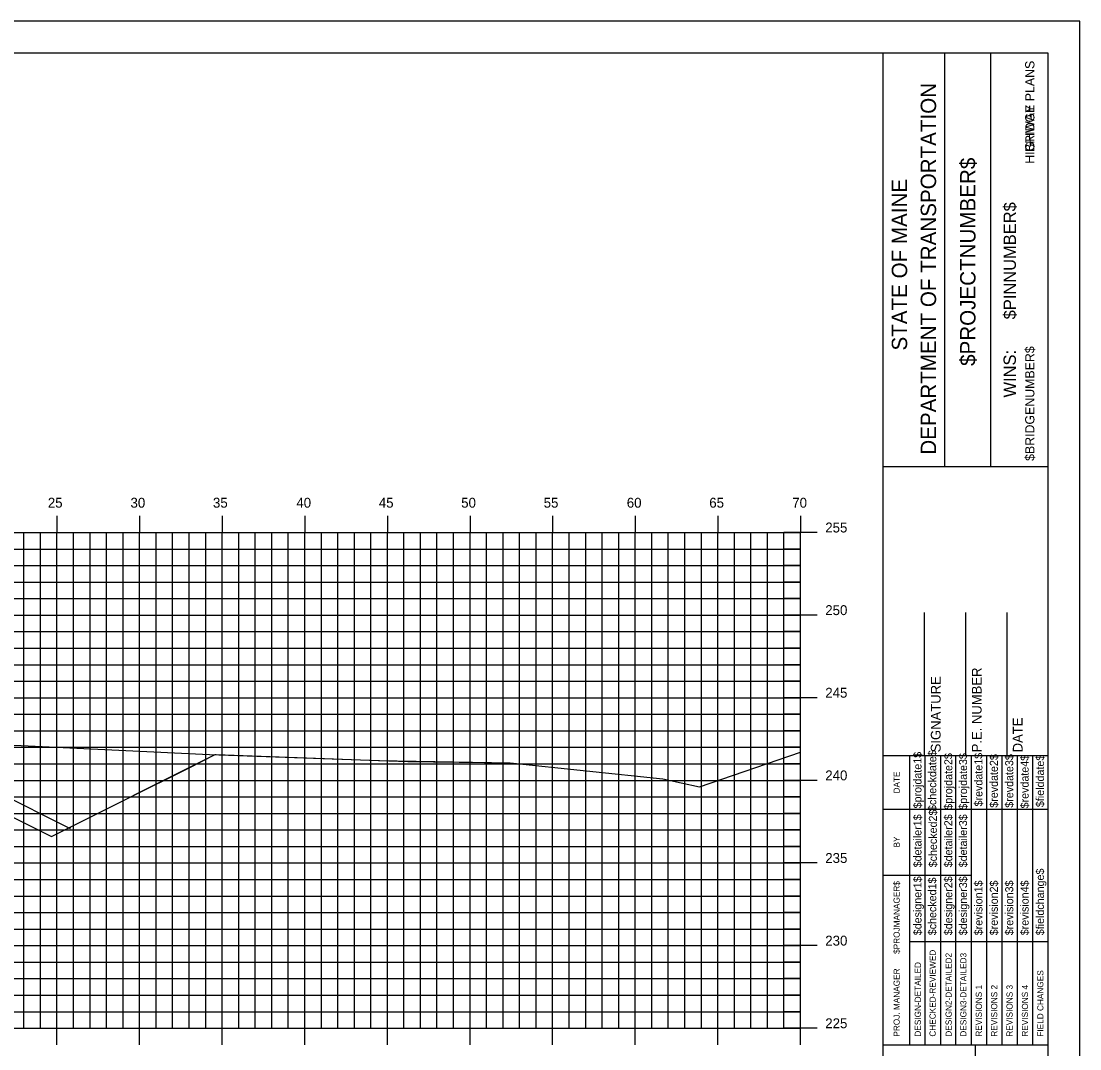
# Model space of a CAD drawing. Extents: x 1168600 to 1177589, y 610178 to 611246.
# Drawn here: x 1173212.4 to 1173276.5, y 610948.3 to 611010.5 of the extents above; entities that cross this region are included whole.
import ezdxf

# ---------------------------------------------------------------- set-up
doc = ezdxf.new("R2010")
doc.units = 0
for name, color, linetype in [('_Construction', 7, 'Continuous'), ('_Station Equation', 7, 'Continuous'), ('BORDER', 7, 'Continuous'), ('D_Text_Standard', 7, 'Continuous'), ('H_V ANNOTATION', 7, 'Continuous'), ('MAJOR', 7, 'Continuous'), ('MINOR', 7, 'Continuous')]:
    doc.layers.add(name, color=color, linetype=linetype)

msp = doc.modelspace()

# ---------------------------------------------------------------- linework, layer by layer
at = {"layer": '_Construction'}
for p, q in [((1173274.585, 611008.596), (1173114.585, 611008.596)), ((1173264.585, 610903.599), (1173264.585, 611008.599)), ((1173268.314, 610983.593), (1173268.314, 611008.593)), ((1173271.109, 610983.593), (1173271.109, 611008.593)), ((1173274.585, 610903.599), (1173274.585, 611008.599)), ((1173264.586, 610983.59), (1173274.585, 610983.59)), ((1173267.085, 610966.099), (1173267.085, 610974.747)), ((1173269.585, 610966.099), (1173269.585, 610974.747)), ((1173272.085, 610966.099), (1173272.085, 610974.747)), ((1173264.585, 610966.099), (1173274.585, 610966.099)), ((1173264.585, 610948.599), (1173274.585, 610948.599)), ((1173270.176, 610913.599), (1173270.176, 610948.599))]:
    msp.add_line(p, q, dxfattribs=at)
msp.add_lwpolyline([(1173106.492, 610900.537), (1173276.492, 610900.537), (1173276.492, 611010.537), (1173106.492, 611010.537)], close=True, dxfattribs=at)
for points in [[(1173266.2, 610962.849), (1173266.2, 610966.099)], [(1173267.132, 610948.602), (1173267.132, 610966.099)], [(1173268.064, 610966.099), (1173268.064, 610948.602)], [(1173268.996, 610948.602), (1173268.996, 610966.099)], [(1173269.928, 610948.602), (1173269.928, 610966.099)], [(1173270.859, 610948.602), (1173270.859, 610966.099)], [(1173271.791, 610948.602), (1173271.791, 610966.099)], [(1173272.723, 610948.602), (1173272.723, 610966.099)], [(1173273.654, 610948.602), (1173273.654, 610966.099)], [(1173266.201, 610948.602), (1173266.201, 610965.393)], [(1173264.585, 610962.849), (1173274.585, 610962.849)], [(1173264.585, 610958.849), (1173266.201, 610958.849)], [(1173266.2, 610958.849), (1173269.927, 610958.849)], [(1173266.2, 610954.849), (1173274.585, 610954.849)]]:
    msp.add_lwpolyline(points, dxfattribs=at)
at = {"layer": '_Station Equation'}
for points in [[(1173119.584, 610974.506), (1173125.722, 610972.617), (1173130.418, 610971.209), (1173135.169, 610970.962), (1173171.23, 610968.586), (1173185.811, 610967.653), (1173195.611, 610967.327), (1173212.422, 610966.698), (1173223.82, 610966.167), (1173235.815, 610965.745), (1173242.003, 610965.653), (1173251.256, 610964.689), (1173253.478, 610964.205), (1173259.584, 610966.307)], [(1173210.871, 610963.945), (1173215.374, 610961.692), (1173215.378, 610961.7), (1173215.424, 610961.784), (1173215.506, 610961.825), (1173215.978, 610962.061), (1173216.23, 610962.187), (1173216.95, 610962.547), (1173218.934, 610963.539), (1173222.535, 610965.339), (1173224.166, 610966.155), (1173224.216, 610966.153), (1173234.051, 610965.807), (1173242.003, 610965.653), (1173251.256, 610964.689), (1173253.478, 610964.205), (1173259.584, 610966.307)]]:
    msp.add_lwpolyline(points, dxfattribs=at)
at = {"layer": 'D_Text_Standard'}
msp.add_lwpolyline([(1173152.164, 610969.842), (1173165.908, 610962.969), (1173170.584, 610965.307), (1173173.584, 610965.367), (1173189.584, 610964.727), (1173205.584, 610964.087), (1173208.584, 610964.027), (1173214.247, 610961.196), (1173224.166, 610966.155)], dxfattribs=at)
at = {"layer": 'MAJOR'}
for p, q in [((1173214.584, 610980.598), (1173214.584, 610979.596)), ((1173219.584, 610980.598), (1173219.584, 610979.596)), ((1173224.584, 610980.598), (1173224.584, 610979.596)), ((1173229.584, 610980.598), (1173229.584, 610979.596)), ((1173234.584, 610980.598), (1173234.584, 610979.596)), ((1173239.584, 610980.598), (1173239.584, 610979.596)), ((1173244.584, 610980.598), (1173244.584, 610979.596)), ((1173249.584, 610980.598), (1173249.584, 610979.596)), ((1173254.584, 610980.598), (1173254.584, 610979.596)), ((1173259.584, 610980.598), (1173259.584, 610979.596)), ((1173119.584, 610979.596), (1173259.584, 610979.596)), ((1173119.584, 610979.596), (1173259.584, 610979.596)), ((1173214.584, 610949.596), (1173214.584, 610979.596)), ((1173219.584, 610949.596), (1173219.584, 610979.596)), ((1173224.584, 610949.596), (1173224.584, 610979.596)), ((1173229.584, 610949.596), (1173229.584, 610979.596)), ((1173234.584, 610949.596), (1173234.584, 610979.596)), ((1173239.584, 610949.596), (1173239.584, 610979.596)), ((1173244.584, 610949.596), (1173244.584, 610979.596)), ((1173249.584, 610949.596), (1173249.584, 610979.596)), ((1173254.584, 610949.596), (1173254.584, 610979.596)), ((1173260.586, 610979.596), (1173258.582, 610979.596)), ((1173259.584, 610949.596), (1173259.584, 610979.596)), ((1173259.584, 610949.596), (1173259.584, 610979.596)), ((1173119.584, 610974.596), (1173259.584, 610974.596)), ((1173260.586, 610974.596), (1173258.582, 610974.596)), ((1173119.584, 610969.596), (1173259.584, 610969.596)), ((1173260.586, 610969.596), (1173258.582, 610969.596)), ((1173119.584, 610964.596), (1173259.584, 610964.596)), ((1173260.586, 610964.596), (1173258.582, 610964.596)), ((1173119.584, 610959.596), (1173259.584, 610959.596)), ((1173260.586, 610959.596), (1173258.582, 610959.596)), ((1173119.584, 610954.596), (1173259.584, 610954.596)), ((1173260.586, 610954.596), (1173258.582, 610954.596)), ((1173119.584, 610949.596), (1173259.584, 610949.596)), ((1173119.584, 610949.596), (1173259.584, 610949.596)), ((1173214.584, 610948.594), (1173214.584, 610949.596)), ((1173219.584, 610948.594), (1173219.584, 610949.596)), ((1173224.584, 610948.594), (1173224.584, 610949.596)), ((1173229.584, 610948.594), (1173229.584, 610949.596)), ((1173234.584, 610948.594), (1173234.584, 610949.596)), ((1173239.584, 610948.594), (1173239.584, 610949.596)), ((1173244.584, 610948.594), (1173244.584, 610949.596)), ((1173249.584, 610948.594), (1173249.584, 610949.596)), ((1173254.584, 610948.594), (1173254.584, 610949.596)), ((1173260.586, 610949.596), (1173258.582, 610949.596)), ((1173259.584, 610948.594), (1173259.584, 610949.596))]:
    msp.add_line(p, q, dxfattribs=at)
at = {"layer": 'MINOR'}
for p, q in [((1173212.584, 610949.596), (1173212.584, 610979.596)), ((1173213.584, 610949.596), (1173213.584, 610979.596)), ((1173215.584, 610949.596), (1173215.584, 610979.596)), ((1173216.584, 610949.596), (1173216.584, 610979.596)), ((1173217.584, 610949.596), (1173217.584, 610979.596)), ((1173218.584, 610949.596), (1173218.584, 610979.596)), ((1173220.584, 610949.596), (1173220.584, 610979.596)), ((1173221.584, 610949.596), (1173221.584, 610979.596)), ((1173222.584, 610949.596), (1173222.584, 610979.596)), ((1173223.584, 610949.596), (1173223.584, 610979.596)), ((1173225.584, 610949.596), (1173225.584, 610979.596)), ((1173226.584, 610949.596), (1173226.584, 610979.596)), ((1173227.584, 610949.596), (1173227.584, 610979.596)), ((1173228.584, 610949.596), (1173228.584, 610979.596)), ((1173230.584, 610949.596), (1173230.584, 610979.596)), ((1173231.584, 610949.596), (1173231.584, 610979.596)), ((1173232.584, 610949.596), (1173232.584, 610979.596)), ((1173233.584, 610949.596), (1173233.584, 610979.596)), ((1173235.584, 610949.596), (1173235.584, 610979.596)), ((1173236.584, 610949.596), (1173236.584, 610979.596)), ((1173237.584, 610949.596), (1173237.584, 610979.596)), ((1173238.584, 610949.596), (1173238.584, 610979.596)), ((1173240.584, 610949.596), (1173240.584, 610979.596)), ((1173241.584, 610949.596), (1173241.584, 610979.596)), ((1173242.584, 610949.596), (1173242.584, 610979.596)), ((1173243.584, 610949.596), (1173243.584, 610979.596)), ((1173245.584, 610949.596), (1173245.584, 610979.596)), ((1173246.584, 610949.596), (1173246.584, 610979.596)), ((1173247.584, 610949.596), (1173247.584, 610979.596)), ((1173248.584, 610949.596), (1173248.584, 610979.596)), ((1173250.584, 610949.596), (1173250.584, 610979.596)), ((1173251.584, 610949.596), (1173251.584, 610979.596)), ((1173252.584, 610949.596), (1173252.584, 610979.596)), ((1173253.584, 610949.596), (1173253.584, 610979.596)), ((1173255.584, 610949.596), (1173255.584, 610979.596)), ((1173256.584, 610949.596), (1173256.584, 610979.596)), ((1173257.584, 610949.596), (1173257.584, 610979.596)), ((1173258.584, 610949.596), (1173258.584, 610979.596)), ((1173119.584, 610978.596), (1173259.584, 610978.596)), ((1173259.584, 610978.596), (1173258.582, 610978.596)), ((1173119.584, 610977.596), (1173259.584, 610977.596)), ((1173259.584, 610977.596), (1173258.582, 610977.596)), ((1173119.584, 610976.596), (1173259.584, 610976.596)), ((1173259.584, 610976.596), (1173258.582, 610976.596)), ((1173119.584, 610975.596), (1173259.584, 610975.596)), ((1173259.584, 610975.596), (1173258.582, 610975.596)), ((1173119.584, 610973.596), (1173259.584, 610973.596)), ((1173259.584, 610973.596), (1173258.582, 610973.596)), ((1173119.584, 610972.596), (1173259.584, 610972.596)), ((1173259.584, 610972.596), (1173258.582, 610972.596)), ((1173119.584, 610971.596), (1173259.584, 610971.596)), ((1173259.584, 610971.596), (1173258.582, 610971.596)), ((1173119.584, 610970.596), (1173259.584, 610970.596)), ((1173259.584, 610970.596), (1173258.582, 610970.596)), ((1173119.584, 610968.596), (1173259.584, 610968.596)), ((1173259.584, 610968.596), (1173258.582, 610968.596)), ((1173119.584, 610967.596), (1173259.584, 610967.596)), ((1173259.584, 610967.596), (1173258.582, 610967.596)), ((1173119.584, 610966.596), (1173259.584, 610966.596)), ((1173259.584, 610966.596), (1173258.582, 610966.596)), ((1173119.584, 610965.596), (1173259.584, 610965.596)), ((1173259.584, 610965.596), (1173258.582, 610965.596)), ((1173119.584, 610963.596), (1173259.584, 610963.596)), ((1173259.584, 610963.596), (1173258.582, 610963.596)), ((1173119.584, 610962.596), (1173259.584, 610962.596)), ((1173259.584, 610962.596), (1173258.582, 610962.596)), ((1173119.584, 610961.596), (1173259.584, 610961.596)), ((1173259.584, 610961.596), (1173258.582, 610961.596)), ((1173119.584, 610960.596), (1173259.584, 610960.596)), ((1173259.584, 610960.596), (1173258.582, 610960.596)), ((1173119.584, 610958.596), (1173259.584, 610958.596)), ((1173259.584, 610958.596), (1173258.582, 610958.596)), ((1173119.584, 610957.596), (1173259.584, 610957.596)), ((1173259.584, 610957.596), (1173258.582, 610957.596)), ((1173119.584, 610956.596), (1173259.584, 610956.596)), ((1173259.584, 610956.596), (1173258.582, 610956.596)), ((1173119.584, 610955.596), (1173259.584, 610955.596)), ((1173259.584, 610955.596), (1173258.582, 610955.596)), ((1173119.584, 610953.596), (1173259.584, 610953.596)), ((1173259.584, 610953.596), (1173258.582, 610953.596)), ((1173119.584, 610952.596), (1173259.584, 610952.596)), ((1173259.584, 610952.596), (1173258.582, 610952.596)), ((1173119.584, 610951.596), (1173259.584, 610951.596)), ((1173259.584, 610951.596), (1173258.582, 610951.596)), ((1173119.584, 610950.596), (1173259.584, 610950.596)), ((1173259.584, 610950.596), (1173258.582, 610950.596))]:
    msp.add_line(p, q, dxfattribs=at)

# ---------------------------------------------------------------- texts
at = {"layer": '_Construction'}
for s, height, p in [('BRIDGE PLANS', 0.55901, (1173273.743, 611002.62)), ('HIGHWAY PLANS', 0.55901, (1173273.743, 611001.911)), ('DEPARTMENT OF TRANSPORTATION', 0.93176, (1173267.792, 610984.302)), ('$PROJECTNUMBER$', 0.93176, (1173270.177, 610989.675)), ('STATE OF MAINE', 0.93176, (1173266.04, 610990.608)), ('$PINNUMBER$', 0.74527, (1173272.622, 610992.493)), ('$BRIDGENUMBER$', 0.55901, (1173273.743, 610983.926)), ('P.E. NUMBER', 0.59055, (1173270.546, 610966.291)), ('SIGNATURE', 0.5906, (1173268.065, 610966.291)), ('DATE', 0.5906, (1173273.026, 610966.291)), ('$projdate1$', 0.48455, (1173266.908, 610962.899)), ('$checkdate$', 0.48455, (1173267.802, 610962.742)), ('$projdate2$', 0.48455, (1173268.771, 610962.821)), ('$projdate3$', 0.48455, (1173269.666, 610962.821)), ('$revdate1$', 0.4845, (1173270.597, 610963.017)), ('$revdate2$', 0.4845, (1173271.529, 610962.939)), ('$revdate3$', 0.4845, (1173272.461, 610962.939)), ('$revdate4$', 0.4845, (1173273.392, 610962.899)), ('$fielddate$', 0.48455, (1173274.324, 610962.978)), ('DATE', 0.3714, (1173265.589, 610963.805)), ('$checked2$', 0.4845, (1173267.84, 610959.334)), ('$detailer1$', 0.48455, (1173266.908, 610959.334)), ('$detailer2$', 0.48455, (1173268.771, 610959.334)), ('$detailer3$', 0.48455, (1173269.666, 610959.334)), ('BY', 0.3714, (1173265.589, 610960.534)), ('$designer1$', 0.48455, (1173266.908, 610955.222)), ('$designer2$', 0.48455, (1173268.771, 610955.222)), ('$designer3$', 0.48455, (1173269.666, 610955.222)), ('$fieldchange$', 0.48455, (1173274.324, 610955.222)), ('$PROJMANAGER$', 0.37275, (1173265.589, 610954.094)), ('$checked1$', 0.4845, (1173267.802, 610955.222)), ('$revision1$', 0.48455, (1173270.597, 610955.222)), ('$revision2$', 0.48455, (1173271.529, 610955.222)), ('$revision3$', 0.48455, (1173272.461, 610955.222)), ('$revision4$', 0.48455, (1173273.392, 610955.222)), ('CHECKED-REVIEWED', 0.37275, (1173267.766, 610949.087)), ('DESIGN2-DETAILED2', 0.37275, (1173268.735, 610949.087)), ('DESIGN3-DETAILED3', 0.37275, (1173269.629, 610949.087)), ('PROJ. MANAGER', 0.37275, (1173265.589, 610949.087)), ('DESIGN-DETAILED', 0.37275, (1173266.872, 610949.087)), ('FIELD CHANGES', 0.37275, (1173274.288, 610949.087)), ('REVISIONS 1', 0.37275, (1173270.561, 610949.087)), ('REVISIONS 2', 0.37275, (1173271.493, 610949.087)), ('REVISIONS 3', 0.37275, (1173272.424, 610949.087)), ('REVISIONS 4', 0.37275, (1173273.356, 610949.087))]:
    msp.add_text(s, height=height, rotation=90, dxfattribs=at).set_placement(p)
at = {"layer": 'BORDER'}
msp.add_text('WINS:', height=0.7453, rotation=90, dxfattribs=at).set_placement((1173272.62, 610987.764))
at = {"layer": 'H_V ANNOTATION'}
for s, p in [('25', (1173214.03, 610981.096)), ('30', (1173219.033, 610981.096)), ('35', (1173224.025, 610981.096)), ('40', (1173229.071, 610981.096)), ('45', (1173234.063, 610981.096)), ('50', (1173239.049, 610981.096)), ('55', (1173244.041, 610981.096)), ('60', (1173249.071, 610981.096)), ('65', (1173254.063, 610981.096)), ('70', (1173259.086, 610981.096)), ('255', (1173261.084, 610979.596)), ('250', (1173261.084, 610974.596)), ('245', (1173261.084, 610969.596)), ('240', (1173261.084, 610964.596)), ('235', (1173261.084, 610959.596)), ('230', (1173261.084, 610954.596)), ('225', (1173261.084, 610949.596))]:
    msp.add_text(s, height=0.6, dxfattribs=at).set_placement(p)

doc.saveas('drawing.dxf')
